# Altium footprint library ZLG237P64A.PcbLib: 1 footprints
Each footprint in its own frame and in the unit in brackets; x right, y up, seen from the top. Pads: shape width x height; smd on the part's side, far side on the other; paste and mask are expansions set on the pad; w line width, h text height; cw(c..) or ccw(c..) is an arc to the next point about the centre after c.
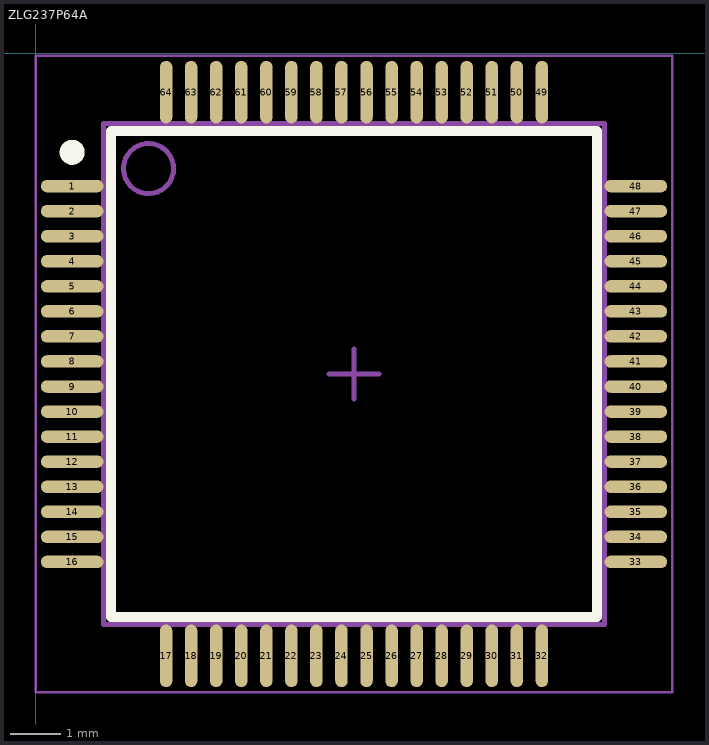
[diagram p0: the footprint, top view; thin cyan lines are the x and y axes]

## ZLG237P64A [mm]
pads (64):
  oval 1.25x0.25 smd mask+0.051: 1(0.731,-2.655) 2(0.731,-3.155) 3(0.731,-3.655) 4(0.731,-4.155) 5(0.731,-4.655) 6(0.731,-5.155) 7(0.731,-5.655) 8(0.731,-6.155) 9(0.731,-6.655) 10(0.731,-7.155) 11(0.731,-7.655) 12(0.731,-8.155) 13(0.731,-8.655) 14(0.731,-9.155) 15(0.731,-9.655) 16(0.731,-10.155) 33(11.981,-10.155) 34(11.981,-9.655) 35(11.981,-9.155) 36(11.981,-8.655) 37(11.981,-8.155) 38(11.981,-7.655) 39(11.981,-7.155) 40(11.981,-6.655) 41(11.981,-6.155) 42(11.981,-5.655) 43(11.981,-5.155) 44(11.981,-4.655) 45(11.981,-4.155) 46(11.981,-3.655) 47(11.981,-3.155) 48(11.981,-2.655)
  oval 0.25x1.25 smd mask+0.051: 17(2.606,-12.03) 18(3.106,-12.03) 19(3.606,-12.03) 20(4.106,-12.03) 21(4.606,-12.03) 22(5.106,-12.03) 23(5.606,-12.03) 24(6.106,-12.03) 25(6.606,-12.03) 26(7.106,-12.03) 27(7.606,-12.03) 28(8.106,-12.03) 29(8.606,-12.03) 30(9.106,-12.03) 31(9.606,-12.03) 32(10.106,-12.03) 49(10.106,-0.78) 50(9.606,-0.78) 51(9.106,-0.78) 52(8.606,-0.78) 53(8.106,-0.78) 54(7.606,-0.78) 55(7.106,-0.78) 56(6.606,-0.78) 57(6.106,-0.78) 58(5.606,-0.78) 59(5.106,-0.78) 60(4.606,-0.78) 61(4.106,-0.78) 62(3.606,-0.78) 63(3.106,-0.78) 64(2.606,-0.78)
Top Overlay:
  circle w0.25: c0.731,-1.98 r0.125
  lines w0.2: 1.506,-11.255 1.506,-1.555 11.206,-1.555 11.206,-11.255 1.506,-11.255
Mechanical 13:
  circle w0.1: c2.256,-2.305 r0.5
  lines w0.1: 1.356,-11.405 1.356,-1.405 11.356,-1.405 11.356,-11.405 1.356,-11.405
Mechanical 15:
  lines w0.05: 0.006,-12.755 0.006,-0.055 12.706,-0.055 12.706,-12.755 0.006,-12.755
  lines w0.1: 5.856,-6.405 6.856,-6.405 ; 6.356,-6.905 6.356,-5.905
3D body: height 1.6, standoff 0.05, extent 1.356,-11.405 11.356,-1.405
